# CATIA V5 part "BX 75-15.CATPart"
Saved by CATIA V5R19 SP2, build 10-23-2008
Part number: BX 75-15
Bounding box of the stored display mesh (mm): x -15.868 to 15.868, y -15.868 to 15.868, z 0 to 90
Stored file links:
  C:\Users\Bora\Desktop\3D Katı model\BX serisi\BX 75\BX 75-15.CATPart
  C:\Program Files\Dassault Systemes\B19\intel_a\reffiles\standard\MetricThickPitch.txt
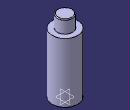
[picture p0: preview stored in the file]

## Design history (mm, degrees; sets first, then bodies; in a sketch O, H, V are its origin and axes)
Body1 (main body)
  Sketch1 on yz-plane, origin (0, 0, 0), H (0, 1, 0), V (0, 0, 1)
    point P1 (9.5, 89)
    point P3 (9.5, 89)
    arc A1 centre (8.5, 89) radius 1 from (9.5, 89) to (8.5, 90) ccw
    line L1 (9.5, 89) -> (9.5, 74)
    line L2 (16, 74) -> (16, 0)
    line L3 (8.5, 90) -> (0, 90)
    point P7 (0, 90)
    line L4 (16, 74) -> (9.5, 74)
    line L5 (16, 0) -> (0, 0)
    tangency: L3 A1
    coincidence: P7 V, P1 P3
    horizontal: L4 H, L5 H
  Shaft1: profile Sketch1, axis Sketch1.V, angle 360
  Sketch2 on face of Shaft1 from Sketch1.L5, origin (0, 0, 0), H (1, 0, 0), V (0, -1, 0)
    point P1 (7.5, 0)
    distance P1 V = 7.5
  Hole1: placed by Sketch2, at (7.5, 0, 0) direction (0, 0, 1), diameter 3.242, depth 5, threaded "M4", thread diameter 4, thread depth 5, pitch 0.7
  Sketch3 on face of Shaft1 from Sketch1.L5, origin (0, 0, 0), H (1, 0, 0), V (0, -1, 0)
    point P1 (-7.5, 0)
    distance P1 V = 7.5
  Hole2: placed by Sketch3, at (-7.5, 0, 0) direction (0, 0, 1), diameter 3.242, depth 5, threaded "M4", thread diameter 4, thread depth 5, pitch 0.7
